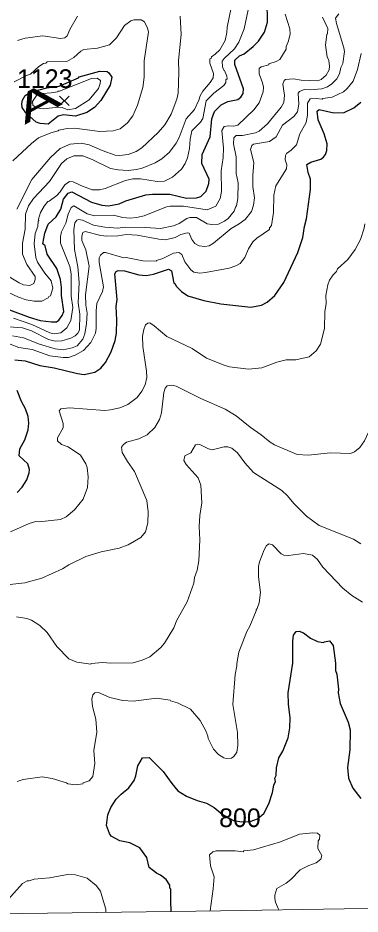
# Model space of a CAD drawing. Extents: x 265.7 to 292.1, y 7676.2 to 7704.2.
# Drawn here: x 271.603 to 273.072, y 7676.25 to 7680.095 of the extents above; entities that cross this region are included whole.
import ezdxf
from ezdxf.enums import TextEntityAlignment as Align

# ---------------------------------------------------------------- set-up
doc = ezdxf.new("R2010")
doc.units = 0
doc.header["$LTSCALE"] = 0.032
for name, color, linetype, lineweight in [('1', 7, 'Continuous', 25), ('2', 7, 'Continuous', 13), ('21', 7, 'Continuous', 25), ('63', 7, 'Continuous', 25)]:
    doc.layers.add(name, color=color, linetype=linetype, lineweight=lineweight)
doc.layers.add('61', color=7, linetype='Continuous')

msp = doc.modelspace()

# ---------------------------------------------------------------- linework, layer by layer
at = {"layer": '1'}
for points in [[(271.7291, 7679.0817), (271.7203, 7679.1168), (271.7107, 7679.1255), (271.7187, 7679.1718), (271.7331, 7679.2093), (271.7674, 7679.2412), (271.7874, 7679.274), (271.7993, 7679.3171), (271.8185, 7679.3426), (271.8352, 7679.349), (271.9198, 7679.3043), (271.9629, 7679.2915), (271.9917, 7679.2883), (272.0379, 7679.2971), (272.0667, 7679.3107), (272.1528, 7679.3354), (272.1816, 7679.3386), (272.255, 7679.3386), (272.3268, 7679.321), (272.3699, 7679.3226), (272.3882, 7679.329), (272.4114, 7679.3514), (272.4225, 7679.3841), (272.4241, 7679.4032), (272.3922, 7679.4703), (272.3938, 7679.5094), (272.4289, 7679.5852), (272.4353, 7679.6618), (272.4473, 7679.6937), (272.4752, 7679.7216), (272.5039, 7679.736), (272.547, 7679.7448), (272.5598, 7679.7551), (272.5694, 7679.7711), (272.571, 7679.7911), (272.5343, 7679.8948), (272.5343, 7679.9139), (272.555, 7679.9323), (272.5742, 7679.9411), (272.6133, 7679.9714), (272.6364, 7679.9945), (272.6611, 7680.0336), (272.6747, 7680.0767), (272.6731, 7680.1685)], [(272.0244, 7678.8574), (272.0299, 7678.8862), (272.0196, 7678.9963), (272.0251, 7679.0067), (272.0339, 7679.0106), (272.0603, 7679.0098), (272.1225, 7678.9923), (272.1544, 7678.9891), (272.1848, 7678.9955), (272.2502, 7679.017), (272.2629, 7679.0098), (272.2725, 7678.9572), (272.2789, 7678.954), (272.2829, 7678.9444), (272.306, 7678.9205), (272.3332, 7678.9021), (272.4018, 7678.8822), (272.4736, 7678.8678), (272.6029, 7678.8542), (272.6492, 7678.8622), (272.6731, 7678.875), (272.7066, 7678.9045), (272.7441, 7678.9596), (272.8048, 7679.0888), (272.8263, 7679.1527), (272.8327, 7679.2006), (272.8423, 7679.2325), (272.859, 7679.3586), (272.859, 7679.4032), (272.8486, 7679.432), (272.8431, 7679.4655), (272.8598, 7679.4758), (272.9029, 7679.4894), (272.9149, 7679.4974), (272.9237, 7679.5094), (272.9292, 7679.5261), (272.9308, 7679.5549), (272.9181, 7679.5979), (272.8925, 7679.657), (272.8878, 7679.6945), (272.8965, 7679.7017), (272.9588, 7679.6881), (273.0035, 7679.6889), (273.045, 7679.7096), (273.0753, 7679.7336)], [(271.7937, 7678.8183), (271.8001, 7678.8351), (271.7906, 7678.9037), (271.7906, 7678.9388), (271.7866, 7678.9723), (271.7698, 7679.0202), (271.7291, 7679.0817)], [(271.9597, 7678.5925), (271.9797, 7678.6164), (272.0036, 7678.6627), (272.0204, 7678.7106), (272.0267, 7678.7425), (272.0283, 7678.8), (272.0244, 7678.8574)], [(271.556, 7678.8463), (271.6517, 7678.8103), (271.6996, 7678.796), (271.7475, 7678.7904), (271.769, 7678.7912), (271.7794, 7678.7984), (271.7937, 7678.8183)], [(271.5903, 7678.6276), (271.6342, 7678.6236), (271.698, 7678.6029), (271.7586, 7678.5941), (271.8592, 7678.5686), (271.8879, 7678.5654), (271.9342, 7678.5749), (271.9597, 7678.5925)], [(271.6006, 7678.0587), (271.6214, 7678.0818), (271.6421, 7678.1137), (271.6517, 7678.1425), (271.6525, 7678.1568), (271.6453, 7678.1816), (271.6094, 7678.2159), (271.6118, 7678.2462), (271.6326, 7678.2845), (271.6469, 7678.3276), (271.6501, 7678.3563), (271.6469, 7678.385), (271.6357, 7678.417), (271.6182, 7678.4489), (271.5998, 7678.4968)], [(272.2606, 7676.2616), (272.2592, 7676.3056), (272.2598, 7676.3566), (272.255, 7676.3614), (272.255, 7676.3742), (272.2398, 7676.3989), (272.2151, 7676.4173), (272.1975, 7676.426), (272.1672, 7676.45), (272.156, 7676.4923), (272.1265, 7676.5338), (272.0834, 7676.5553), (272.0411, 7676.5641), (272.0036, 7676.5848), (271.9964, 7676.596), (271.9837, 7676.6295), (271.9892, 7676.6758), (272.0028, 7676.7077), (272.0252, 7676.7428), (272.0459, 7676.7652), (272.0794, 7676.7923), (272.1018, 7676.8234), (272.1097, 7676.8434), (272.1177, 7676.8865), (272.1385, 7676.9208), (272.1672, 7676.9224), (272.227, 7676.8617), (272.2637, 7676.8099), (272.2901, 7676.7787), (272.3268, 7676.7556), (272.3731, 7676.7372), (272.4122, 7676.7261), (272.4449, 7676.7069), (272.4794, 7676.6782), (272.5284, 7676.6518), (272.5642, 7676.6461), (272.6, 7676.648), (272.632, 7676.6593), (272.6584, 7676.682), (272.6803, 7676.7237), (272.6954, 7676.7716), (272.7018, 7676.8035), (272.7082, 7676.8194), (272.7066, 7676.8338), (272.7114, 7676.845), (272.713, 7676.8769), (272.7234, 7676.92), (272.7401, 7676.9487), (272.7625, 7677.0062), (272.7704, 7677.0493), (272.7712, 7677.0923), (272.7641, 7677.1514), (272.7625, 7677.1993), (272.7832, 7677.3269), (272.7832, 7677.4211), (272.7864, 7677.4474), (272.7968, 7677.4618), (272.8104, 7677.4642), (272.8295, 7677.457), (272.859, 7677.4339), (272.8886, 7677.4195), (272.9133, 7677.4147), (272.9189, 7677.4187), (272.9404, 7677.4227), (272.9556, 7677.4019), (272.966, 7677.3269), (272.9667, 7677.295), (272.9715, 7677.2791), (272.9795, 7677.2152), (272.9779, 7677.1993), (272.9859, 7677.153), (273.021, 7677.0732), (273.029, 7677.0413), (273.0274, 7676.9551), (273.0178, 7676.8785), (273.0218, 7676.8338), (273.041, 7676.7907), (273.0753, 7676.746)]]:
    msp.add_lwpolyline(points, dxfattribs=at)
msp.add_lwpolyline([(271.7279, 7679.7947), (271.7807, 7679.8022), (271.864, 7679.8381), (271.8664, 7679.8421), (271.9549, 7679.866), (271.9861, 7679.8645), (271.9932, 7679.8597), (272.006, 7679.8405), (271.9996, 7679.8062), (271.9597, 7679.74), (271.9326, 7679.7097), (271.8991, 7679.6889), (271.8512, 7679.6729), (271.7985, 7679.6793), (271.7762, 7679.6729), (271.7339, 7679.6394), (271.6996, 7679.6418), (271.682, 7679.6482), (271.6381, 7679.6873), (271.6214, 7679.7105), (271.6198, 7679.7256), (271.623, 7679.7416), (271.6349, 7679.7623), (271.6613, 7679.7775)], close=True, dxfattribs=at)
at = {"layer": '2'}
for points in [[(271.5512, 7678.9923), (271.6086, 7678.958), (271.6278, 7678.95), (271.6549, 7678.9468), (271.6717, 7678.9548), (271.678, 7678.9723), (271.6772, 7678.9859), (271.6413, 7679.0362), (271.6238, 7679.0809), (271.623, 7679.1287), (271.6342, 7679.1878), (271.6358, 7679.2532), (271.6485, 7679.2883), (271.6701, 7679.3203), (271.7387, 7679.3929), (271.7906, 7679.4703), (271.8129, 7679.4902), (271.8432, 7679.503), (271.8815, 7679.503), (271.9214, 7679.4878), (272.0012, 7679.4487), (272.0331, 7679.4423), (272.0762, 7679.4399), (272.1129, 7679.4439), (272.1369, 7679.4503), (272.1927, 7679.4727), (272.2215, 7679.4902), (272.2534, 7679.5189), (272.2821, 7679.558), (272.2949, 7679.582), (272.326, 7679.6618), (272.3619, 7679.7025), (272.3803, 7679.7416), (272.3858, 7679.7607), (272.397, 7679.7799), (272.4289, 7679.8174), (272.4409, 7679.8373), (272.4433, 7679.8565), (272.4265, 7679.9012), (272.4273, 7679.9187), (272.4321, 7679.9211), (272.4337, 7679.9275), (272.4505, 7679.9387), (272.4696, 7679.9578), (272.4928, 7679.9985), (272.4999, 7680.032), (272.5007, 7680.0544), (272.5191, 7680.1374)], [(272.5909, 7680.1294), (272.575, 7680.048), (272.5518, 7679.9905), (272.5327, 7679.9626), (272.4888, 7679.9211), (272.48, 7679.9091), (272.4808, 7679.8852), (272.4864, 7679.8708), (272.4904, 7679.8693), (272.4999, 7679.8453), (272.5007, 7679.8333), (272.496, 7679.8286), (272.496, 7679.8174), (272.4864, 7679.8046), (272.4441, 7679.7719), (272.4114, 7679.7384), (272.397, 7679.6634), (272.3866, 7679.6482), (272.3491, 7679.6099), (272.342, 7679.574), (272.3396, 7679.5341), (272.3308, 7679.4942), (272.3212, 7679.4703), (272.3052, 7679.4455), (272.2661, 7679.4112), (272.2326, 7679.3945), (272.2007, 7679.3929), (272.1289, 7679.404), (272.097, 7679.404), (272.0651, 7679.3977), (271.9773, 7679.3625), (271.9533, 7679.357), (271.9214, 7679.3578), (271.8736, 7679.3753), (271.84, 7679.3913), (271.8249, 7679.3929), (271.8041, 7679.3793), (271.785, 7679.349), (271.7698, 7679.3322), (271.7379, 7679.3091), (271.7315, 7679.3075), (271.7156, 7679.2875), (271.7004, 7679.2596), (271.6924, 7679.2309), (271.6932, 7679.2245), (271.6908, 7679.2237), (271.6884, 7679.1998), (271.678, 7679.1702), (271.6733, 7679.1256), (271.6804, 7679.0665), (271.6868, 7679.0474), (271.7187, 7678.9995), (271.7467, 7678.9667), (271.7539, 7678.9356), (271.7427, 7678.9029), (271.7363, 7678.8997), (271.7339, 7678.8933), (271.706, 7678.8798), (271.6725, 7678.879), (271.639, 7678.8854), (271.6054, 7678.8973), (271.56, 7678.9189)], [(272.9109, 7680.0975), (272.9332, 7680.0496), (272.9324, 7680.0265), (272.9292, 7680.0257), (272.9229, 7679.9778), (272.93, 7679.9283), (272.9372, 7679.9123), (272.9404, 7679.8884), (272.9388, 7679.8724), (272.9269, 7679.8485), (272.9053, 7679.8301), (272.8902, 7679.8254), (272.8183, 7679.8278), (272.7864, 7679.8333), (272.7513, 7679.8301), (272.7457, 7679.8262), (272.7409, 7679.8102), (272.7473, 7679.7639), (272.7449, 7679.7312), (272.733, 7679.7113), (272.6747, 7679.641), (272.6388, 7679.6091), (272.6236, 7679.6019), (272.5678, 7679.5908), (272.5406, 7679.5908), (272.5303, 7679.5804), (272.5279, 7679.5549), (272.5398, 7679.499), (272.5406, 7679.4272), (272.5486, 7679.3873), (272.5478, 7679.3203), (272.5414, 7679.2891), (272.5367, 7679.2835), (272.5311, 7679.266), (272.5055, 7679.2349), (272.4904, 7679.2221), (272.464, 7679.2101), (272.4353, 7679.2085), (272.4162, 7679.2117), (272.3699, 7679.2381), (272.3412, 7679.2381), (272.3284, 7679.2349), (272.2949, 7679.2133), (272.2709, 7679.2029), (272.2151, 7679.191), (272.1512, 7679.1958), (272.0635, 7679.1966), (272.0315, 7679.1934), (271.9757, 7679.1966), (271.9278, 7679.2053), (271.8799, 7679.2269), (271.864, 7679.2293), (271.856, 7679.2269), (271.8472, 7679.2157), (271.8432, 7679.1862), (271.8464, 7679.1016), (271.86, 7679.0266), (271.8664, 7678.9596), (271.8616, 7678.8718), (271.8696, 7678.8239), (271.8672, 7678.7553), (271.86, 7678.7417), (271.8496, 7678.7314), (271.8305, 7678.721), (271.7922, 7678.7098), (271.7634, 7678.7074), (271.7347, 7678.7154), (271.6621, 7678.7529), (271.623, 7678.7657), (271.5049, 7678.7736)], [(271.5879, 7679.8206), (271.6405, 7679.8476), (271.6575, 7679.8533), (271.6932, 7679.8868), (271.7132, 7679.8988), (271.7235, 7679.9012), (271.7283, 7679.9068), (271.8137, 7679.9083), (271.8432, 7679.9251), (271.8735, 7679.9522), (271.8863, 7679.9594), (271.9454, 7679.965), (271.9964, 7679.9794), (272.0268, 7680.0089), (272.0603, 7680.0624), (272.0874, 7680.0815), (272.1002, 7680.0863), (272.1321, 7680.0863), (272.1464, 7680.0775), (272.16, 7680.0512), (272.164, 7680.0352), (272.1457, 7679.9107), (272.1457, 7679.8405), (272.1393, 7679.7958), (272.1169, 7679.72), (272.0962, 7679.6746), (272.0738, 7679.6442), (272.0419, 7679.6195), (272.0124, 7679.6099), (271.9549, 7679.6075), (271.8464, 7679.6219), (271.8145, 7679.6203), (271.7786, 7679.6131), (271.7762, 7679.6099), (271.7443, 7679.6019), (271.6916, 7679.5796), (271.6613, 7679.5564), (271.5815, 7679.4822)], [(271.6014, 7679.9985), (271.6342, 7680.0073), (271.7108, 7680.0177), (271.7858, 7680.0065), (271.8049, 7680.0097), (271.8153, 7680.0177), (271.8265, 7680.0448), (271.8592, 7680.1023)], [(271.8089, 7679.2149), (271.8193, 7679.2532), (271.8313, 7679.2812), (271.844, 7679.2883), (271.9007, 7679.254), (271.9326, 7679.246), (272.014, 7679.2492), (272.0539, 7679.2381), (272.0858, 7679.2357), (272.1129, 7679.2381), (272.1449, 7679.246), (272.2406, 7679.2843), (272.2566, 7679.2875), (272.314, 7679.2867), (272.4162, 7679.2708), (272.4521, 7679.2875), (272.472, 7679.3195), (272.4776, 7679.3506), (272.476, 7679.4384), (272.484, 7679.4958), (272.4856, 7679.5357), (272.4792, 7679.6123), (272.488, 7679.6283), (272.5071, 7679.6323), (272.5295, 7679.6299), (272.547, 7679.6346), (272.6164, 7679.7009), (272.6388, 7679.7304), (272.6563, 7679.7783), (272.6571, 7679.7974), (272.6532, 7679.8166), (272.638, 7679.8549), (272.638, 7679.878), (272.6476, 7679.8844), (272.6795, 7679.894), (272.6803, 7679.8972), (272.7114, 7679.9076), (272.7274, 7679.9163), (272.7545, 7679.961), (272.7545, 7679.9722), (272.7633, 7679.9921), (272.7721, 7680.0257), (272.7697, 7680.048), (272.7505, 7680.1102)], [(272.2997, 7680.1023), (272.3036, 7680.0241), (272.2925, 7679.9123), (272.2941, 7679.8613), (272.2909, 7679.7719), (272.2853, 7679.7464), (272.2614, 7679.6825), (272.2342, 7679.6362), (272.2047, 7679.6027), (272.1353, 7679.5373), (272.1113, 7679.5221), (272.0762, 7679.5094), (272.0387, 7679.5038), (272.0204, 7679.5062), (271.9645, 7679.5253), (271.9087, 7679.5509)], [(272.5183, 7679.1918), (272.5526, 7679.2109), (272.579, 7679.2301), (272.6061, 7679.2644), (272.6149, 7679.2915), (272.6188, 7679.3234), (272.6117, 7679.3713), (272.6109, 7679.4192), (272.6164, 7679.4751), (272.6021, 7679.5309), (272.6077, 7679.5469), (272.6149, 7679.5533), (272.6827, 7679.5644), (272.7122, 7679.5844), (272.7393, 7679.6347), (272.788, 7679.6722), (272.8032, 7679.6913), (272.8096, 7679.724), (272.8056, 7679.7719), (272.8112, 7679.7791), (272.8311, 7679.7879), (272.8582, 7679.7863), (272.9077, 7679.7902), (272.9316, 7679.799), (272.9508, 7679.8126), (272.9723, 7679.8341), (272.9835, 7679.8549), (272.9891, 7679.882), (272.9979, 7679.8996), (273.0043, 7679.9506), (273.0027, 7679.9666), (272.9707, 7680.0703), (272.9668, 7680.0943), (272.9811, 7680.1126)], [(273.0609, 7679.874), (273.0769, 7679.9419)], [(272.9085, 7679.7456), (272.9125, 7679.7488), (272.9524, 7679.7551), (273.0003, 7679.7775), (273.017, 7679.7918), (273.0418, 7679.8238), (273.0609, 7679.874)], [(271.5368, 7678.7074), (271.607, 7678.6811), (271.6645, 7678.6723), (271.7411, 7678.6444), (271.7969, 7678.6372), (271.8209, 7678.638), (271.8496, 7678.6476), (271.8847, 7678.6675), (271.9166, 7678.7026), (271.9358, 7678.7425), (271.9398, 7678.7617), (271.939, 7678.8383), (271.9422, 7678.8694), (271.9669, 7678.9213), (271.9701, 7678.9404), (271.9517, 7679.0458), (271.9525, 7679.0649), (271.9573, 7679.0769), (271.9709, 7679.0888), (271.9789, 7679.0888), (272.0579, 7679.0657), (272.0682, 7679.0673), (272.1401, 7679.0529), (272.1975, 7679.0513), (272.1975, 7679.0537), (272.2247, 7679.0625), (272.2709, 7679.0849), (272.2933, 7679.088), (272.3068, 7679.0793), (272.3196, 7679.0481), (272.3459, 7679.0146), (272.3579, 7679.0043), (272.3842, 7679.0003), (272.4082, 7679.0019), (272.5103, 7679.0218), (272.5391, 7679.0306), (272.5574, 7679.041), (272.5774, 7679.0665), (272.5925, 7679.1048), (272.6109, 7679.1335), (272.6292, 7679.1503), (272.6827, 7679.187), (272.6835, 7679.1942), (272.6915, 7679.2037), (272.7002, 7679.2596), (272.7018, 7679.3346), (272.7098, 7679.3745), (272.7553, 7679.4479), (272.7569, 7679.4639), (272.7505, 7679.4862), (272.7513, 7679.5038), (272.7561, 7679.5134), (272.776, 7679.5277), (272.7984, 7679.5509), (272.8127, 7679.5979), (272.8407, 7679.6458), (272.8463, 7679.6777), (272.8455, 7679.7296), (272.8574, 7679.7472), (272.8854, 7679.7496), (272.9085, 7679.7456)], [(271.9087, 7679.5509), (271.8751, 7679.558), (271.8273, 7679.5525), (271.785, 7679.5341), (271.7435, 7679.4966), (271.6629, 7679.4016), (271.599, 7679.274)], [(271.8321, 7678.9005), (271.8321, 7678.9963), (271.8257, 7679.0282), (271.7866, 7679.1287), (271.7866, 7679.1575), (271.7906, 7679.1766), (271.8089, 7679.2149)], [(272.9707, 7679.0067), (272.9755, 7679.0186), (273.0194, 7679.0585), (273.0505, 7679.1008), (273.0737, 7679.1447), (273.0896, 7679.1926), (273.0928, 7679.2117)], [(271.5799, 7678.7314), (271.6278, 7678.7226), (271.6964, 7678.6954), (271.7634, 7678.6747), (271.7969, 7678.6707), (271.8368, 7678.6787), (271.8576, 7678.6883), (271.8815, 7678.717), (271.8911, 7678.7393), (271.8983, 7678.784), (271.8999, 7678.8287), (271.8943, 7678.8622), (271.8935, 7678.9069), (271.9095, 7679.0298), (271.8943, 7679.0992), (271.8775, 7679.1399), (271.8775, 7679.1591), (271.8815, 7679.1742), (271.8927, 7679.1782), (271.9597, 7679.1607), (271.9853, 7679.1583), (272.0315, 7679.1599), (272.0699, 7679.1654), (272.1145, 7679.1631), (272.2087, 7679.1455), (272.2374, 7679.1431), (272.2789, 7679.1527), (272.3029, 7679.1662), (272.33, 7679.1734), (272.338, 7679.171), (272.3491, 7679.1447)], [(272.3491, 7679.1447), (272.3627, 7679.1263), (272.3811, 7679.1168), (272.405, 7679.1144), (272.4241, 7679.1168), (272.4433, 7679.1287), (272.5183, 7679.1918)], [(271.5711, 7677.8895), (271.6517, 7677.9262), (271.6804, 7677.9342), (271.6932, 7677.9326), (271.7858, 7677.943), (271.8105, 7677.9549), (271.8464, 7677.9837), (271.8839, 7678.0307), (271.9023, 7678.0802), (271.9055, 7678.1265), (271.8999, 7678.1664), (271.8943, 7678.1824), (271.8727, 7678.2191), (271.8193, 7678.255), (271.7906, 7678.2653), (271.7738, 7678.2797), (271.7738, 7678.2933), (271.7977, 7678.3356), (271.7969, 7678.3547), (271.781, 7678.409), (271.7874, 7678.4178), (271.8241, 7678.4217), (271.9757, 7678.4106), (272.0012, 7678.413), (272.0411, 7678.4225), (272.0754, 7678.4361), (272.1145, 7678.4656), (272.1353, 7678.4928), (272.1496, 7678.5207), (272.156, 7678.5526), (272.1552, 7678.5797), (272.1401, 7678.6851), (272.1385, 7678.7298), (272.1433, 7678.7585), (272.1512, 7678.7776), (272.1608, 7678.7856), (272.1688, 7678.7864), (272.1879, 7678.7744), (272.243, 7678.7282), (272.3507, 7678.6771), (272.4122, 7678.6356), (272.488, 7678.6045), (272.5119, 7678.5981), (272.5933, 7678.5877), (272.6508, 7678.5933), (272.7146, 7678.6172), (272.7545, 7678.6284), (272.796, 7678.6284), (272.8534, 7678.6412), (272.8838, 7678.6667), (272.9013, 7678.6947), (272.9189, 7678.7617), (272.9205, 7678.8335), (272.9261, 7678.8702), (272.9245, 7678.9037), (272.934, 7678.95), (272.9412, 7678.9692), (272.9556, 7678.9923), (272.9707, 7679.0067)], [(271.5847, 7678.8072), (271.6629, 7678.78), (271.7411, 7678.7441), (271.7586, 7678.7393), (271.7874, 7678.7441), (271.8129, 7678.7649), (271.8305, 7678.7968), (271.8384, 7678.8527), (271.8321, 7678.9005)], [(272.1225, 7678.2885), (272.1576, 7678.306), (272.1903, 7678.338), (272.2111, 7678.3723), (272.2199, 7678.401), (272.2294, 7678.4872), (272.2358, 7678.5063)], [(272.2358, 7678.5063), (272.2438, 7678.5159), (272.2646, 7678.5199), (272.2829, 7678.5151), (272.389, 7678.4624), (272.4928, 7678.4162), (272.5406, 7678.3874), (272.5997, 7678.3388), (272.6476, 7678.306), (272.6859, 7678.2741), (272.705, 7678.263), (272.8016, 7678.2223), (272.8487, 7678.2191), (272.9444, 7678.2294), (273.0306, 7678.2262), (273.0482, 7678.2334), (273.0713, 7678.2518), (273.0912, 7678.2797), (273.108, 7678.318), (273.1112, 7678.3372), (273.1503, 7678.4712), (273.1774, 7678.5191), (273.195, 7678.5382)], [(271.5177, 7677.6589), (271.6326, 7677.6717), (271.706, 7677.6908), (271.7954, 7677.7315), (271.8225, 7677.7491), (271.8943, 7677.7842), (271.9613, 7677.8049), (272.0379, 7677.8201), (272.0762, 7677.8336), (272.1305, 7677.8664), (272.1512, 7677.8903), (272.1616, 7677.9286), (272.1624, 7677.9765), (272.156, 7678.0244), (272.1034, 7678.1488), (272.073, 7678.1919), (272.0515, 7678.2302), (272.0475, 7678.2526), (272.0563, 7678.2645), (272.0698, 7678.2741), (272.1225, 7678.2885)], [(272.3803, 7677.7658), (272.3842, 7677.8552), (272.381, 7677.9127), (272.3842, 7677.9605), (272.3922, 7678.0148), (272.3882, 7678.0898), (272.3763, 7678.1217), (272.3252, 7678.1792), (272.3156, 7678.1959), (272.3204, 7678.2159), (272.3451, 7678.2294), (272.3659, 7678.263), (272.3731, 7678.2661), (272.3834, 7678.2645), (272.421, 7678.2454), (272.4369, 7678.2422), (272.488, 7678.2542), (272.5047, 7678.2542), (272.5215, 7678.2494), (272.5462, 7678.2286), (272.5766, 7678.1856), (272.6141, 7678.1449), (272.7354, 7678.0674), (272.7609, 7678.0451), (272.788, 7678.0116), (272.8423, 7677.9573), (272.8965, 7677.9166), (273.0434, 7677.8584), (273.0753, 7677.8392)], [(271.9246, 7676.8402), (271.9334, 7676.896), (271.9294, 7676.9519), (271.9414, 7677.0301), (271.9374, 7677.086), (271.923, 7677.1402), (271.9206, 7677.1721), (271.9246, 7677.1913), (271.9342, 7677.1993), (271.9493, 7677.2009), (271.998, 7677.1793), (272.0539, 7677.1666), (272.0986, 7677.1642), (272.1991, 7677.1769), (272.2574, 7677.1681), (272.2582, 7677.165), (272.2885, 7677.157), (272.3436, 7677.129), (272.385, 7677.0812), (272.4098, 7677.0365), (272.4186, 7677.0141), (272.4194, 7677.003), (272.4433, 7676.9583), (272.464, 7676.9344), (272.4864, 7676.9208), (272.4976, 7676.9176), (272.5199, 7676.9192), (272.5303, 7676.9256), (272.543, 7676.9447), (272.5478, 7676.9727), (272.5462, 7677.0285), (272.5263, 7677.1498), (272.5351, 7677.2775), (272.543, 7677.3158), (272.5422, 7677.3254), (272.551, 7677.3732), (272.5853, 7677.4626), (272.5989, 7677.4849), (272.626, 7677.5504), (272.6252, 7677.556), (272.63, 7677.5615), (272.6388, 7677.5855), (272.6444, 7677.6302), (272.6356, 7677.6972), (272.6364, 7677.7419), (272.6404, 7677.761), (272.6595, 7677.8121), (272.6699, 7677.8313), (272.6811, 7677.8392), (272.6962, 7677.8337), (272.733, 7677.7961), (272.7449, 7677.7906), (272.7641, 7677.7882), (272.8295, 7677.7977), (272.867, 7677.7906), (272.8886, 7677.7714), (272.9125, 7677.7387), (272.9979, 7677.6485), (273.037, 7677.6174), (273.0817, 7677.5887)], [(272.2725, 7677.4786), (272.2853, 7677.5105), (272.3292, 7677.5903), (272.3579, 7677.6701), (272.3619, 7677.694), (272.3731, 7677.7259), (272.3803, 7677.7658)], [(271.5975, 7677.5248), (271.6421, 7677.5177), (271.6613, 7677.5113), (271.698, 7677.4889), (271.7283, 7677.4578), (271.7698, 7677.3988), (271.8217, 7677.3453), (271.856, 7677.3309), (271.9166, 7677.323), (271.9182, 7677.3253), (271.9677, 7677.3301), (272.0028, 7677.3261), (272.0986, 7677.3277), (272.1369, 7677.3389), (272.1688, 7677.3541), (272.2167, 7677.3932), (272.2326, 7677.4131), (272.2725, 7677.4786)], [(271.6006, 7676.8194), (271.6254, 7676.8282), (271.7076, 7676.8386), (271.7507, 7676.8322), (271.8121, 7676.8139)], [(271.8121, 7676.8139), (271.8177, 7676.8091), (271.8512, 7676.8051), (271.8815, 7676.8091), (271.8831, 7676.8131), (271.9087, 7676.8218), (271.9246, 7676.8402)], [(272.4284, 7676.2642), (272.4417, 7676.3582), (272.4457, 7676.4101), (272.4297, 7676.4572), (272.4249, 7676.5042), (272.4393, 7676.5178), (272.4545, 7676.5218), (272.5359, 7676.521), (272.5702, 7676.5178), (272.5726, 7676.521), (272.6141, 7676.5258), (272.7306, 7676.5601), (272.812, 7676.5928), (272.8694, 7676.5992), (272.8886, 7676.5968), (272.8989, 7676.5888), (272.8973, 7676.5713), (272.8925, 7676.5641), (272.8909, 7676.5322), (272.9069, 7676.5011), (272.9037, 7676.4851), (272.8838, 7676.4699), (272.8519, 7676.4588), (272.8143, 7676.4404), (272.7752, 7676.3989), (272.7545, 7676.383), (272.7146, 7676.3598), (272.7054, 7676.3319), (272.7054, 7676.3164), (272.7092, 7676.3013), (272.7203, 7676.2747), (272.7234, 7676.268)], [(271.5678, 7676.2521), (271.5559, 7676.2612), (271.5494, 7676.2708), (271.5467, 7676.2778), (271.546, 7676.2874), (271.5486, 7676.2963), (271.5726, 7676.3262), (271.6238, 7676.3814), (271.6437, 7676.3925), (271.6517, 7676.3925), (271.6725, 7676.4005), (271.7395, 7676.4053), (271.8161, 7676.4205), (271.8512, 7676.4189), (271.9007, 7676.4045), (271.939, 7676.3734), (271.9573, 7676.3478), (271.9709, 7676.304), (271.98, 7676.2707), (271.9813, 7676.2578)]]:
    msp.add_lwpolyline(points, dxfattribs=at)
msp.add_lwpolyline([(271.7818, 7679.7807), (271.7746, 7679.7807), (271.773, 7679.7775), (271.7459, 7679.7727), (271.7076, 7679.7711), (271.6836, 7679.7623), (271.6661, 7679.7368), (271.6677, 7679.7208), (271.6836, 7679.7089), (271.7124, 7679.7049), (271.7778, 7679.7112), (271.793, 7679.7097), (271.8177, 7679.7009), (271.8512, 7679.7057), (271.9087, 7679.7432), (271.9494, 7679.7926), (271.9565, 7679.8134), (271.9573, 7679.8262), (271.9438, 7679.8365), (271.9198, 7679.8349)], close=True, dxfattribs=at)
at = {"layer": '21'}
for p, q in [((271.7823, 7679.7595), (271.8235, 7679.7183)), ((271.8235, 7679.7595), (271.7823, 7679.7183))]:
    msp.add_line(p, q, dxfattribs=at)
at = {"layer": '63', "lineweight": 13}
msp.add_lwpolyline([(280.4306, 7676.3719), (279.9, 7676.3649), (279.3695, 7676.3578), (278.839, 7676.3508), (278.3084, 7676.3437), (277.7779, 7676.3366), (277.2473, 7676.3295), (276.7168, 7676.3224), (276.1862, 7676.3153), (275.6557, 7676.3081), (275.1251, 7676.3009), (274.5946, 7676.2937), (274.064, 7676.2865), (273.5335, 7676.2793), (273.0029, 7676.2721), (272.4723, 7676.2648), (271.9418, 7676.2575), (271.4112, 7676.2502)], dxfattribs=at)

# ---------------------------------------------------------------- texts
at = {"layer": '61'}
for s, p in [('1123', (271.7187, 7679.7942)), ('800', (272.5561, 7676.6235))]:
    msp.add_text(s, height=0.08, dxfattribs=at).set_placement(p, align=Align.CENTER)
at = {"layer": '61', "width": 1.75}
msp.add_text('A', height=0.12, rotation=28.436, dxfattribs=at).set_placement((271.7147, 7679.6806), align=Align.CENTER)

doc.saveas('drawing.dxf')
